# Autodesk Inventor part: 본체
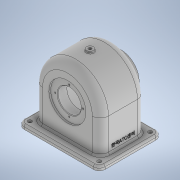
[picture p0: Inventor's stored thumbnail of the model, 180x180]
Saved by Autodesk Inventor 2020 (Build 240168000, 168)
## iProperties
Created: 2022-09
Part Number: 본체
Material: 일반
Document SubType Name: Modeling
Designer: Administrator
Density: 1 g/cm^3
Appearance: 기본값
Author: Administrator
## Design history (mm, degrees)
sketch "스케치1"
  geometry: L1 (-70, 54)-(70, 54); L2 (70, 54)-(70, -54); L3 (70, -54)-(-70, -54); L4 (-70, -54)-(-70, 54); L5 (-70, 54)-(70, -54); L6 (70, 54)-(-70, -54); 1 further point
  constraints: 12 end point, 2 midpoint, 2 parallel, 1 horizontal, 1 perpendicular
  dimensions: "d0" = 140 distance of L1.start L1.end; "d1" = 108 distance of L3.end L1.start
extrude "돌출1" new body sketch "스케치1" distance "d2" = 7; taper "d3" = 0 deg
fillet "모깎기1" dims "d4" = 10
sketch "스케치2"
  geometry: C1 r 3.3 at (60, -44); A1 r 10 centre (60, -44) between (60, -54) and (70, -44) reference; 1 further point
  constraints: 1 centre point, 1 coincident
  dimensions: "d5" = 6.6 diameter of C1
extrude "돌출2" cut sketch "스케치2" extent not by distance; stored distance "d6" = 0; taper "d7" = 0 deg
sketch "스케치3"
  geometry: L1 (-60, 7)-(60, 7) reference; L2 (57, 64)-(57, 7); L3 (-57, 64)-(-57, 7); A1 r 57 centre (0, 64) between (57, 64) and (-57, 64); 1 further point
  constraints: 4 end point, 2 perpendicular, 2 point on circle, 2 point on line, 2 tangent, 1 centre point, 1 vertical alignment
  dimensions: "d12" = 57 radius of A1; "d13" = 64 distance of point (0, 0) A1.centre
extrude "돌출3" join sketch "스케치3" stored distance "d15" = 78; taper "d16" = 0 deg
node "작업 평면1"
sketch "스케치5"
  geometry: C1 r 6 at (0, 0); 1 further point
  constraints: 1 centre point, 1 coincident
  dimensions: "d22" = 12 diameter of C1
extrude "돌출5" join sketch "스케치5" stored distance "d23" = 68; taper "d24" = 0 deg
sketch "스케치7"
  geometry: C1 r 31 at (0, -64); A1 r 57 centre (0, -64) between (-57, -64) and (57, -64) reference; 1 further point
  constraints: 1 centre point, 1 coincident
  dimensions: "d25" = 62 diameter of C1
extrude "돌출6" join sketch "스케치7" distance "d26" = 15; taper "d27" = 0 deg
sketch "스케치8"
  geometry: L1 (-39, 64)-(64.281, 64); L2 (-39, 64)-(-39, 96); L3 (-39, 96)-(-36, 96); L4 (-36, 96)-(-36, 84); L5 (-36, 84)-(-20, 84); L6 (-20, 84)-(-20, 92); L7 (-20, 92)-(-34, 100.083); L8 (-34, 100.083)-(-34, 116); L9 (-34, 116)-(34, 116); L10 (34, 116)-(34, 81.5); L11 (34, 81.5)-(38, 81.5); L12 (38, 81.5)-(38, 84); L13 (54, 33)-(54, 95) reference; L14 (38, 84)-(54, 84); L15 (54, 64)-(54, 84); L16 (39, 64)-(39, 121) reference; L17 (-39, 121)-(39, 121) reference; L18 (-39, 121)-(-39, 64) reference; 2 further points
  constraints: 28 end point, 9 perpendicular, 2 vertical, 1 collinear, 1 horizontal, 1 midpoint, 1 point on line
  dimensions: "d28" = 16 distance of L4.end L5.end; "d29" = 16 distance of L12.end L14.end; "d30" = 40 diameter of L14 L1; "d31" = 35 diameter of L11 L1; "d32" = 5 distance between parallel lines of L16 L10; "d34" = 5 distance between parallel lines of L17 L9; "d35" = 5 distance between parallel lines of L18 L8; "d36" = 60 deg angle of L6 L7; "d37" = 56 diameter of L6.end L1; "d38" = 14 horizontal distance of L6.end L8.end; "d39" = 40 diameter of L5 L1; "d40" = 64 diameter of L3 L1
revolve "회전1" sketch "스케치8" stored, may be unused: angle "d41" = 90 deg
chamfer "모따기1" distance "d42" = 1; stored, may be unused: second distance "d43" = 2, angle "d44" = 45 deg
fillet "모깎기2" dims "d45" = 3
sketch "스케치9"
  geometry: C1 r 6 at (0, 0) reference; 2 further points
  constraints: 1 coincident
hole "구멍1" sketch "스케치9" at (0, 0) diameter "d46" = 5.1881; stored, may be unused: countersink angle "d50" = 90 deg, drill point angle "d52" = 0 deg; dims "d47" = 12, "d48" = 4, "d49" = 2, "d51" = 8
fillet "모깎기3" dims "d53" = 1
fillet "모깎기4" dims "d54" = 14
fillet "모깎기5" dims "d55" = 3
sketch "스케치10"
  geometry: L1 (64, -19)-(64, 69) reference; L2 (0, -14)-(54, -14) reference; 3 further points
  constraints: 1 horizontal alignment, 1 midpoint, 1 other
  dimensions: "d56" = 17 distance from line of L1 point (47, 25); "d84" = 39 distance from line of L2 point (47, 25) (derived)
feature "엠보싱1" sketch "스케치10" dims "d0" = 140, "d1" = 108, "d57" = 0.5, "d58" = 0
sketch "스케치11" dims "d59" = 48
  geometry: C1 r 21 at (0, 0) reference; 3 further points
  constraints: 1 coincident, 1 vertical alignment, 2 other
hole "구멍2" sketch "스케치11" at (0, -24) diameter "d60" = 2.459; stored, may be unused: countersink angle "d64" = 90 deg, drill point angle "d66" = 118 deg; dims "d61" = 7, "d62" = 4, "d63" = 2, "d65" = 9
sketch "스케치12" dims "d70" = 48
  geometry: C1 r 21 at (0, 0) reference; 3 further points
  constraints: 1 coincident, 1 vertical alignment, 2 other
hole "구멍3" sketch "스케치12" at (0, 24) diameter "d71" = 2.459; stored, may be unused: countersink angle "d75" = 90 deg, drill point angle "d77" = 118 deg; dims "d72" = 7, "d73" = 4, "d74" = 2, "d76" = 9
fillet "모깎기6" dims "d81" = 9
fillet "모깎기7" dims "d82" = 3, "d83" = 0.6
fillet "모깎기8" dims "d85" = 3
node "솔리드1"
pattern_linear "직사각형 패턴1"
pattern_circular "원형 패턴1" dims angle "d68" = 360 deg
pattern_circular "원형 패턴2" dims angle "d79" = 360 deg
feature "A9D066F2-1C7D-4E18-AEED-F7BC21143FA4" dims "d60" = 2.459, "d61" = 7, "d62" = 4, "d63" = 2, "d64" = 90 deg, "d65" = 9, "d66" = 118 deg
other parameters: "d21" = 124
